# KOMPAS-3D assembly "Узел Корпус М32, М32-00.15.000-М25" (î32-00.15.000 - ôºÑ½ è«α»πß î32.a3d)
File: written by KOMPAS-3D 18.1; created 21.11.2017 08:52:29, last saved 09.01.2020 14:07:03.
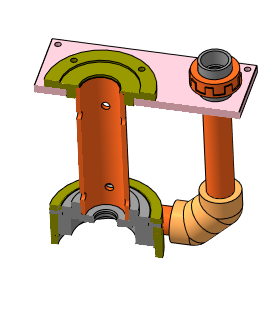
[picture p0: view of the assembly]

Document properties: Автор: Милов; Организация: Милов; Полное имя файла: D:\Magna\Магна Ins\Магна ins 32\Для Караби Магна 32\М32-00.15.000 - Узел Корпус М32.a3d

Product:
- Part/product: Узел Корпус М32  | designation М32-00.15.000-М25  | pos. 0
    Масса: 9.06193
    Раздел спецификации: Сборочные единицы
    Форматы листов документа: A3
  - Component [detail]: Колено 90 @2~63 ф.FV Plast  | pos. 9  | Масса: 0.37; Раздел спецификации: Прочие изделия; source file: ..\..\..\..\1 ПКИ 3D\Полипропиленовые фитинги, трубы\Колено 90 ф63 ф.FV Plast.m3d
  - Component [detail]: Фланец  | designation М32-00.15.001  | pos. 5  | Материал: Полипропилен  ГОСТ 26996-86 (density 900 kg/m3); Масса: 0.816359; Раздел спецификации: Детали; Форматы листов документа: A3; source file: М32-00.15.001 - Фланец.m3d
  - Component [assembly]: Корпус  | designation М32-00.20.000  | pos. 1  | Материал: Полипропилен  ГОСТ 26996-86 (density 900 kg/m3); Масса: 2.99454; Раздел спецификации: Сборочные единицы; Форматы листов документа: A3; source file: ..\М32-00.20.000 - Корпус.a3d, ..\М32-00.20.000 - Корпус.cdw
  - Component [assembly]: Колонна  | designation М32-00.22.000  | pos. 2  | Масса: 0.990487; Раздел спецификации: Сборочные единицы; Форматы листов документа: A3; Примечание: см. заказ; source file: М32-00.22.000 - Колонна.a3d, М32-00.22.000 - Колонна.cdw
  - Component [detail]: Труба 63 PN10 S=5,8 FV PPR ф. FV PLAST  | pos. 11  | Материал: Полипропилен  ГОСТ 26996-86 (density 900 kg/m3); Масса: 0.152669; Раздел спецификации: Прочие изделия; Примечание: мм
  - Component [detail]: Основание  | designation М32-00.15.002-М25  | pos. 6  | Материал: Полипропилен  ГОСТ 26996-86 (density 900 kg/m3); Масса: 1.82071; Раздел спецификации: Детали; Форматы листов документа: A3
  - Component [assembly]: Муфта разборная ф63 РР  | pos. 10  | Масса: 1.69089; Раздел спецификации: Прочие изделия
- Part/product: Узел Корпус М32  | designation М32-00.15.000  | pos. 0
    Масса: 9.86598
    Раздел спецификации: Сборочные единицы
    Форматы листов документа: A3
    source file: М32-00.15.000 - Корпус М32.cdw
  - Component [assembly]: Муфта разборная ф63 РР  | pos. 11  | Масса: 1.69089; Раздел спецификации: Прочие изделия
  - Component [detail]: Основание  | designation М32-00.15.002  | pos. 6  | Материал: Полипропилен  ГОСТ 26996-86 (density 900 kg/m3); Масса: 2.27958; Раздел спецификации: Детали; Форматы листов документа: A3; source file: М32-00.15.002 - Основание.cdw, М32-00.15.002 - Основание.m3d, М32-00.15.002-М25 - Основание.cdw
  - Component [detail]: Колено 45 63 FV PPR ф. "FV PLAST"  | qty 2  | pos. 10  | Материал: Полипропилен  ГОСТ 26996-86 (density 900 kg/m3); Масса: 0.34448; Раздел спецификации: Прочие изделия
  - Component [detail]: Труба 63 PN10 S=5,8 FV PPR ф. FV PLAST  | pos. 0  | Материал: Полипропилен  ГОСТ 26996-86 (density 900 kg/m3); Масса: 0.051404; Раздел спецификации: Прочие изделия; Примечание: м
  - Component [detail]: Труба 63 PN10 S=5,8 FV PPR ф. FV PLAST  | pos. 11  | Материал: Полипропилен  ГОСТ 26996-86 (density 900 kg/m3); Масса: 0.324558; Раздел спецификации: Прочие изделия; Примечание: мм
  - Component [detail]: Колонна  | designation М32-00.22.001  | pos. 2  | Масса: 0.990487; Раздел спецификации: Сборочные единицы; Форматы листов документа: A3; Примечание: см. заказ; source file: М32-00.22.000 - Колонна.cdw, М32-00.22.001 - Колонна.m3d
  - Component [assembly]: Узел Корпус  | designation М32-00.20.000  | pos. 1  | Материал: Полипропилен  ГОСТ 26996-86 (density 900 kg/m3); Масса: 3.02375; Раздел спецификации: Сборочные единицы; Форматы листов документа: A3; source file: М32-00.20.000 - Корпус.cdw, М32-00.20.000 - Узел Корпус.a3d
  - Component [detail]: Фланец  | designation М32-00.15.001  | pos. 5  | Материал: Полипропилен  ГОСТ 26996-86 (density 900 kg/m3); Масса: 0.816359; Раздел спецификации: Детали; Форматы листов документа: A3; source file: М32-00.15.001 - Фланец.cdw, М32-00.15.001 - Фланец.m3d
- Part/product: Корпус М32 с косячным корпусом М40  | designation М32-00.15.000-666  | pos. 0
    Масса: 9.75067
    Раздел спецификации: Сборочные единицы
    Форматы листов документа: A3
  - Component [detail]: Труба 63 PN10 S=5,8 FV PPR ф. FV PLAST  | designation 1001  | pos. 11  | Материал: Полипропилен  ГОСТ 26996-86 (density 900 kg/m3); Масса: 0.324558; Раздел спецификации: Прочие изделия; Примечание: мм
  - Component [detail]: Колено 45@1~ @2~63 FV PPR ф. "FV PLAST"  | qty 2  | pos. 10  | Материал: Полипропилен  ГОСТ 26996-86 (density 900 kg/m3); Масса: 0.34448; Раздел спецификации: Прочие изделия
  - Component [detail]: Труба 63 PN10 S=5,8 FV PPR ф. FV PLAST  | designation М32колено  | pos. 0  | Материал: Полипропилен  ГОСТ 26996-86 (density 900 kg/m3); Масса: 0.051404; Раздел спецификации: Прочие изделия; Примечание: м
  - Component [assembly]: Муфта разборная ф63 РР  | pos. 11  | Масса: 1.69089; Раздел спецификации: Прочие изделия
  - Component [assembly]: Корпус косячный ММ32  | designation М40-00.30.000-666  | pos. 17  | Материал: Полипропилен  ГОСТ 26996-86 (density 900 kg/m3); Масса: 2.90843; Раздел спецификации: Сборочные единицы; source file: ..\..\Магна ins 40\3Д\М40-00.30.000 - Корпус.a3d

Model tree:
1. Сечение поверхностью:1  (with: Операция выдавливания:1, Операция выдавливания:3, Операция вращения:1, Отверстие:1, Вырезать элемент выдавливания:1, Вырезать элемент выдавливания:2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)  (labels: ..\М32-00.20.000 - Корпус.a3d; D:\Magna\Магна Ins\Магна ins 32\М32-00.20.000 - Корпус.a3d)

Referenced files in D:\Magna\Магна Ins\Магна ins 32\Для Караби Магна 32\: М32-00.15.001 - Фланец.m3d, М32-00.15.001 - Фланец.cdw, М32-00.20.000 - Узел Корпус.a3d, М32-00.20.000 - Корпус.cdw, М32-00.22.001 - Колонна.m3d, М32-00.22.000 - Колонна.cdw, М32-00.15.002 - Основание.m3d, М32-00.15.002 - Основание.cdw, М32-00.15.002-М25 - Основание.cdw, М32-00.22.000 - Колонна.a3d, Труба 63 PN10 S=5,8 FV PPR ф. FV PLAST.m3d, Колено 45гр 63 FV PPR ф. FV PLAST.m3d, Муфта разборная ф63 РР.a3d
Referenced files in D:\Magna\Магна Ins\Магна ins 32\: М32-00.20.000 - Корпус.cdw, М32-00.15.000 - Корпус М32.cdw, М32-00.22.000 - Колонна.a3d, М32-00.15.001 - Фланец.m3d, М32-00.15.002 - Основание.m3d, М32-00.22.001 - Колонна.m3d
Referenced files in D:\1 ПКИ 3D\Полипропиленовые фитинги, трубы\: Колено 90 ф63 ф.FV Plast.m3d, Колено 45гр 63 FV PPR ф. FV PLAST.m3d
Referenced files in D:\Magna\Магна Ins\Магна ins 40\3Д\: М40-00.30.000 - Корпус.a3d
Referenced files in D:\1 ПКИ 3D\Полипропиленовые фитинги, трубы\Трубы\: Труба 63 PN10 S=5,8 FV PPR ф. FV PLAST.m3d
Referenced files in D:\1 ПКИ 3D\Полипропиленовые фитинги, трубы\Разборные муфты\: Муфта разборная ф63 РР.a3d
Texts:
  Корпус М32
  Точка начала. Х
  Точка начала. Y
  Точка начала. Z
